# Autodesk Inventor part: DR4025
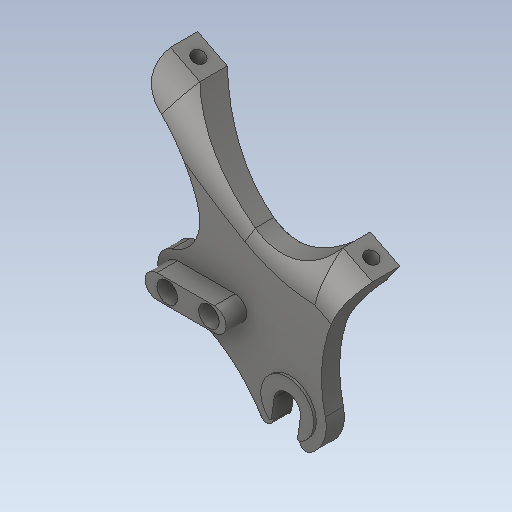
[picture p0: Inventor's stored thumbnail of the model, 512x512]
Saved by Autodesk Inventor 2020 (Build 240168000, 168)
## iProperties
Created: 2015-11
Part Number: DR4025
Material: Ogólny
Document SubType Name: Modeling
Designer: Tomasz
Density: 1 g/cm^3
Appearance: Domyślna
Sending System: SolidWorks 2017
Last Author: Tomasz
Last Saved: 2017-09-17
Author: Tomasz
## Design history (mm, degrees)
feature "Imported1"
node "Bryła1"
